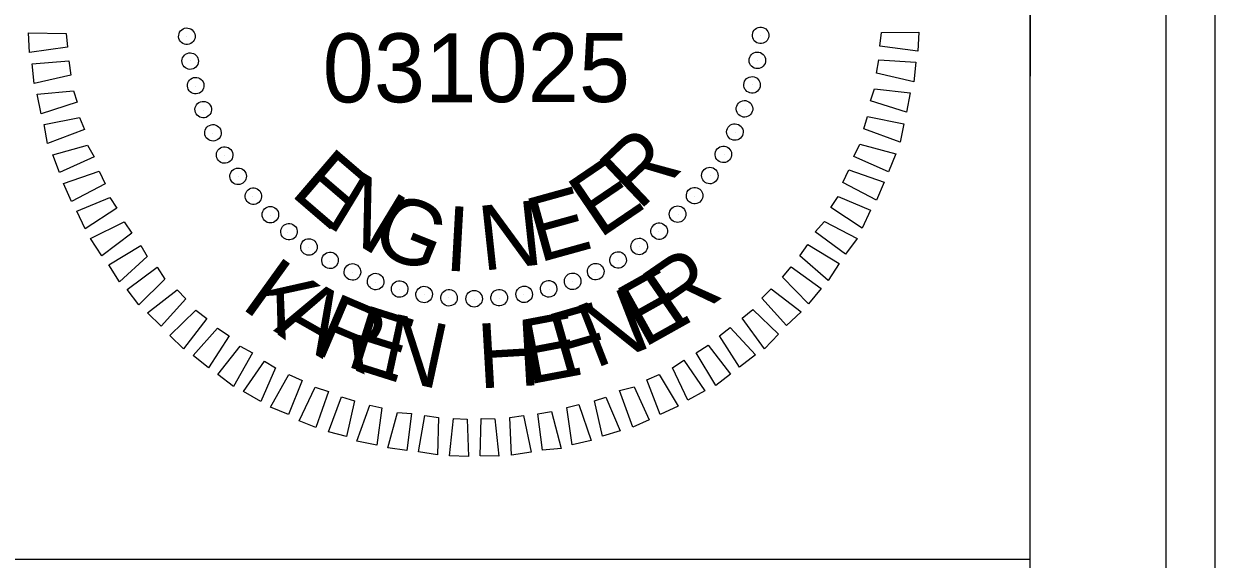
# Model space of a CAD drawing. Extents: x 2568837 to 2570520, y 536545 to 537640.
# Drawn here: x 2570410.9 to 2570520.2, y 537467.1 to 537516.2 of the extents above; entities that cross this region are included whole.
import ezdxf

# ---------------------------------------------------------------- set-up
doc = ezdxf.new("R2010")
doc.units = 0
for name, color, linetype in [('Default', 7, 'Continuous'), ('Sheet Plan CELL', 7, 'Continuous'), ('Sheet Plan Layout CELL', 7, 'Continuous'), ('Sheet Plot Border Inside CELL', 7, 'Continuous'), ('Sheet Plot Border Outside CELL', 7, 'Continuous')]:
    doc.layers.add(name, color=color, linetype=linetype)

msp = doc.modelspace()

# ---------------------------------------------------------------- linework, layer by layer
at = {"layer": 'Default'}
for p, q in [((2570425.81, 537515.02), (2570425.81, 537515.02)), ((2570425.81, 537515.02), (2570425.81, 537515.02)), ((2570478.5, 537515.12), (2570478.5, 537515.12)), ((2570478.5, 537515.12), (2570478.5, 537515.12)), ((2570426.17, 537512.81), (2570426.17, 537512.81)), ((2570426.17, 537512.81), (2570426.17, 537512.81)), ((2570478.17, 537512.85), (2570478.17, 537512.85)), ((2570478.17, 537512.85), (2570478.17, 537512.85)), ((2570426.63, 537510.5), (2570426.63, 537510.5)), ((2570426.63, 537510.5), (2570426.63, 537510.5)), ((2570477.74, 537510.63), (2570477.74, 537510.63)), ((2570477.74, 537510.63), (2570477.74, 537510.63)), ((2570427.31, 537508.3), (2570427.31, 537508.3)), ((2570427.31, 537508.3), (2570427.31, 537508.3)), ((2570477.05, 537508.4), (2570477.05, 537508.4)), ((2570477.05, 537508.4), (2570477.05, 537508.4)), ((2570428.19, 537506.16), (2570428.19, 537506.16)), ((2570428.19, 537506.16), (2570428.19, 537506.16)), ((2570476.14, 537506.27), (2570476.14, 537506.27)), ((2570476.14, 537506.27), (2570476.14, 537506.27)), ((2570429.28, 537504.18), (2570429.28, 537504.18)), ((2570429.28, 537504.18), (2570429.28, 537504.18)), ((2570475.12, 537504.2), (2570475.12, 537504.2)), ((2570475.12, 537504.2), (2570475.12, 537504.2)), ((2570430.53, 537502.2), (2570430.53, 537502.2)), ((2570430.53, 537502.2), (2570430.53, 537502.2)), ((2570473.84, 537502.28), (2570473.84, 537502.28)), ((2570473.84, 537502.28), (2570473.84, 537502.28)), ((2570431.88, 537500.38), (2570431.88, 537500.38)), ((2570431.88, 537500.38), (2570431.88, 537500.38)), ((2570472.45, 537500.35), (2570472.45, 537500.35)), ((2570472.45, 537500.35), (2570472.45, 537500.35)), ((2570433.5, 537498.67), (2570433.5, 537498.67)), ((2570433.5, 537498.67), (2570433.5, 537498.67)), ((2570470.91, 537498.74), (2570470.91, 537498.74)), ((2570470.91, 537498.74), (2570470.91, 537498.74)), ((2570435.1, 537497.12), (2570435.1, 537497.12)), ((2570435.1, 537497.12), (2570435.1, 537497.12)), ((2570469.14, 537497.13), (2570469.14, 537497.13)), ((2570469.14, 537497.13), (2570469.14, 537497.13)), ((2570437.03, 537495.74), (2570437.03, 537495.74)), ((2570437.03, 537495.74), (2570437.03, 537495.74)), ((2570467.38, 537495.78), (2570467.38, 537495.78)), ((2570467.38, 537495.78), (2570467.38, 537495.78)), ((2570438.95, 537494.45), (2570438.95, 537494.45)), ((2570438.95, 537494.45), (2570438.95, 537494.45)), ((2570465.4, 537494.53), (2570465.4, 537494.53)), ((2570465.4, 537494.53), (2570465.4, 537494.53)), ((2570441.02, 537493.39), (2570441.02, 537493.39)), ((2570441.02, 537493.39), (2570441.02, 537493.39)), ((2570463.36, 537493.44), (2570463.36, 537493.44)), ((2570463.36, 537493.44), (2570463.36, 537493.44)), ((2570443.1, 537492.48), (2570443.1, 537492.48)), ((2570443.1, 537492.48), (2570443.1, 537492.48)), ((2570445.38, 537491.84), (2570445.38, 537491.84)), ((2570445.38, 537491.84), (2570445.38, 537491.84)), ((2570459.07, 537491.88), (2570459.07, 537491.88)), ((2570459.07, 537491.88), (2570459.07, 537491.88)), ((2570461.22, 537492.56), (2570461.22, 537492.56)), ((2570461.22, 537492.56), (2570461.22, 537492.56)), ((2570447.6, 537491.4), (2570447.6, 537491.4)), ((2570447.6, 537491.4), (2570447.6, 537491.4)), ((2570449.87, 537491.08), (2570449.87, 537491.08)), ((2570449.87, 537491.08), (2570449.87, 537491.08)), ((2570452.19, 537490.96), (2570452.19, 537490.96)), ((2570452.19, 537490.96), (2570452.19, 537490.96)), ((2570454.51, 537491.06), (2570454.51, 537491.06)), ((2570454.51, 537491.06), (2570454.51, 537491.06)), ((2570456.76, 537491.42), (2570456.76, 537491.42)), ((2570456.76, 537491.42), (2570456.76, 537491.42))]:
    msp.add_line(p, q, dxfattribs=at)
for points in [[(2570414.87, 537514.08), (2570411.4, 537513.59), (2570411.31, 537515.38), (2570414.74, 537515.34)], [(2570489.56, 537515.43), (2570492.99, 537515.44), (2570492.91, 537513.7), (2570489.42, 537514.17)], [(2570415.18, 537511.5), (2570411.82, 537510.75), (2570411.63, 537512.54), (2570415, 537512.81)], [(2570489.34, 537512.9), (2570492.72, 537512.7), (2570492.54, 537510.91), (2570489.1, 537511.68)], [(2570488.92, 537510.26), (2570492.2, 537509.9), (2570491.86, 537508.1), (2570488.57, 537509.14)], [(2570415.75, 537509.04), (2570412.45, 537507.97), (2570412.1, 537509.76), (2570415.42, 537510.08)], [(2570416.43, 537506.52), (2570413.03, 537505.24), (2570412.73, 537506.97), (2570415.99, 537507.62)], [(2570488.28, 537507.71), (2570491.62, 537507.04), (2570491.28, 537505.35), (2570487.94, 537506.6)], [(2570417.32, 537504.01), (2570414.14, 537502.57), (2570413.53, 537504.2), (2570416.72, 537505.1)], [(2570487.59, 537505.17), (2570490.88, 537504.29), (2570490.22, 537502.64), (2570487.04, 537504.06)], [(2570418.32, 537501.55), (2570415.24, 537499.91), (2570414.52, 537501.58), (2570417.77, 537502.7)], [(2570486.58, 537502.83), (2570489.82, 537501.69), (2570489.11, 537500.04), (2570486.03, 537501.66)], [(2570419.41, 537499.3), (2570416.5, 537497.4), (2570415.73, 537499.02), (2570418.76, 537500.29)], [(2570485.58, 537500.39), (2570488.55, 537499.13), (2570487.79, 537497.48), (2570484.91, 537499.38)], [(2570484.35, 537498.1), (2570487.34, 537496.53), (2570486.26, 537495.08), (2570483.48, 537497.14)], [(2570420.78, 537497.01), (2570418.02, 537494.95), (2570416.99, 537496.52), (2570420.07, 537498.05)], [(2570482.81, 537495.97), (2570485.69, 537494.23), (2570484.67, 537492.68), (2570482.09, 537494.95)], [(2570422.19, 537494.87), (2570419.65, 537492.56), (2570418.67, 537494.12), (2570421.59, 537495.87)], [(2570423.81, 537492.8), (2570421.43, 537490.43), (2570420.35, 537491.84), (2570423.1, 537493.89)], [(2570481.27, 537493.94), (2570484.05, 537491.93), (2570482.86, 537490.54), (2570480.5, 537492.97)], [(2570425.74, 537490.99), (2570423.47, 537488.47), (2570422.23, 537489.71), (2570424.93, 537491.82)], [(2570479.46, 537491.9), (2570482.19, 537489.79), (2570480.85, 537488.55), (2570478.59, 537491.04)], [(2570427.67, 537489.18), (2570425.51, 537486.4), (2570424.27, 537487.64), (2570426.65, 537489.95)], [(2570477.76, 537490.02), (2570480.12, 537487.75), (2570478.83, 537486.41), (2570476.78, 537489.21)], [(2570429.7, 537487.59), (2570427.81, 537484.66), (2570426.41, 537485.79), (2570428.63, 537488.31)], [(2570475.68, 537488.35), (2570478, 537485.87), (2570476.54, 537484.73), (2570474.7, 537487.59)], [(2570431.84, 537486.05), (2570430.1, 537482.96), (2570428.66, 537484.04), (2570430.72, 537486.66)], [(2570473.66, 537486.73), (2570475.72, 537484.08), (2570474.36, 537483.05), (2570472.57, 537486.03)], [(2570433.97, 537484.66), (2570432.61, 537481.58), (2570431.01, 537482.5), (2570432.96, 537485.28)], [(2570471.42, 537485.37), (2570473.37, 537482.56), (2570471.81, 537481.69), (2570470.38, 537484.67)], [(2570436.42, 537483.5), (2570435.16, 537480.37), (2570433.51, 537481.07), (2570435.19, 537484.06)], [(2570469.18, 537484.06), (2570470.92, 537481.15), (2570469.25, 537480.38), (2570468.03, 537483.57)], [(2570438.81, 537482.49), (2570437.66, 537479.2), (2570436.12, 537479.8), (2570437.59, 537482.89)], [(2570466.88, 537482.91), (2570468.26, 537479.89), (2570466.74, 537479.22), (2570465.52, 537482.57)], [(2570441.2, 537481.64), (2570440.47, 537478.36), (2570438.82, 537478.8), (2570440.03, 537481.99)], [(2570464.27, 537481.97), (2570465.59, 537478.89), (2570463.97, 537478.38), (2570463.22, 537481.63)], [(2570443.73, 537481), (2570443.27, 537477.57), (2570441.42, 537477.95), (2570442.62, 537481.24)], [(2570459.28, 537480.66), (2570460.19, 537477.26), (2570458.46, 537477.12), (2570458.02, 537480.43)], [(2570461.8, 537481.29), (2570462.92, 537477.99), (2570461.19, 537477.59), (2570460.7, 537481.01)], [(2570446.43, 537480.47), (2570446.02, 537477.09), (2570444.28, 537477.33), (2570445.17, 537480.56)], [(2570448.92, 537480.1), (2570448.82, 537476.67), (2570447.08, 537476.96), (2570447.65, 537480.29)], [(2570451.55, 537479.94), (2570451.67, 537476.52), (2570449.93, 537476.59), (2570450.29, 537480.02)], [(2570454.08, 537479.99), (2570454.46, 537476.57), (2570452.73, 537476.59), (2570452.82, 537480.02)], [(2570456.71, 537480.3), (2570457.41, 537476.94), (2570455.62, 537476.64), (2570455.45, 537480.12)]]:
    msp.add_lwpolyline(points, close=True, dxfattribs=at)
for centre, major_axis in [((2570425.83, 537515.08), (-0.756, -0.067)), ((2570478.48, 537515.16), (0.756, -0.065)), ((2570426.13, 537512.8), (-0.747, -0.133)), ((2570478.18, 537512.87), (0.747, -0.131)), ((2570426.64, 537510.55), (-0.733, -0.197)), ((2570477.69, 537510.62), (0.733, -0.195)), ((2570427.33, 537508.35), (-0.713, -0.26)), ((2570477, 537508.42), (0.713, -0.258)), ((2570428.22, 537506.22), (-0.687, -0.322)), ((2570476.12, 537506.29), (0.688, -0.32)), ((2570429.29, 537504.18), (-0.656, -0.38)), ((2570475.06, 537504.24), (0.658, -0.378)), ((2570430.53, 537502.23), (-0.621, -0.436)), ((2570473.82, 537502.3), (0.622, -0.434)), ((2570431.93, 537500.41), (-0.58, -0.488)), ((2570472.42, 537500.46), (0.582, -0.487)), ((2570433.49, 537498.71), (-0.536, -0.537)), ((2570470.86, 537498.76), (0.537, -0.536)), ((2570435.2, 537497.15), (-0.487, -0.582)), ((2570469.17, 537497.2), (0.488, -0.58)), ((2570437.03, 537495.75), (-0.434, -0.622)), ((2570467.34, 537495.8), (0.436, -0.621)), ((2570438.97, 537494.52), (-0.378, -0.658)), ((2570465.4, 537494.56), (0.38, -0.656)), ((2570441.02, 537493.46), (-0.32, -0.688)), ((2570463.35, 537493.49), (0.322, -0.687)), ((2570443.15, 537492.58), (-0.258, -0.713)), ((2570445.35, 537491.89), (-0.195, -0.733)), ((2570459.03, 537491.91), (0.197, -0.733)), ((2570461.23, 537492.6), (0.26, -0.713)), ((2570447.6, 537491.39), (-0.131, -0.747)), ((2570449.89, 537491.09), (-0.065, -0.756)), ((2570452.19, 537491), (0.001, -0.759)), ((2570454.49, 537491.1), (0.067, -0.756)), ((2570456.78, 537491.4), (0.133, -0.747))]:
    msp.add_ellipse(centre, major_axis=major_axis, ratio=0.999708, dxfattribs=at)
at = {"layer": 'Sheet Plan CELL'}
for points in [[(2570503.22, 537617.15), (2569003.18, 537617.15), (2569003.18, 536567.15), (2570503.19, 536567.15)], [(2570403.19, 537579.59), (2570503.18, 537579.6), (2570503.19, 537467.09), (2570403.19, 537467.08)]]:
    msp.add_lwpolyline(points, close=True, dxfattribs=at)
at = {"layer": 'Sheet Plan Layout CELL'}
msp.add_lwpolyline([(2570263.93, 537405.66), (2570503.2, 537405.66), (2570503.23, 537617.15), (2570263.93, 537617.15)], close=True, dxfattribs=at)
at = {"layer": 'Sheet Plot Border Inside CELL'}
msp.add_lwpolyline([(2568849.69, 536564.64), (2570515.68, 536564.65), (2570515.69, 537619.64), (2568849.69, 537619.64)], close=True, dxfattribs=at)
at = {"layer": 'Sheet Plot Border Outside CELL'}
msp.add_lwpolyline([(2568836.69, 536544.64), (2570520.19, 536544.64), (2570520.19, 537639.64), (2568836.69, 537639.64)], close=True, dxfattribs=at)

# ---------------------------------------------------------------- texts
at = {"layer": 'Default'}
for s, height, rotation, p in [('031025', 6.322, 0.081, (2570438.29, 537509.01)), ('R', 5.94, 43.5624, (2570467.32, 537498.99)), ('E', 5.94, 319.3578, (2570435.2, 537500.6)), ('E', 5.94, 34.205, (2570463.67, 537496.45)), ('N', 5.94, 328.7149, (2570438.41, 537497.82)), ('G', 5.94, 338.0712, (2570442.46, 537495.52)), ('E', 5.94, 15.4927, (2570458.13, 537494.29)), ('I', 5.94, 356.7822, (2570449.4, 537493.6)), ('N', 5.94, 6.1373, (2570452.93, 537493.56)), ('R', 5.94, 34.4906, (2570470.5, 537488)), ('K', 5.94, 324.2363, (2570430.68, 537490.22)), ('E', 5.94, 29.2101, (2570467.72, 537486.44)), ('A', 5.94, 330.3893, (2570433.72, 537488.07)), ('N', 5.94, 21.2433, (2570463.28, 537484.58)), ('R', 5.94, 336.9555, (2570437.2, 537486.16)), ('F', 5.94, 16.0317, (2570460.25, 537483.71)), ('E', 5.94, 342.5116, (2570440.29, 537484.85)), ('N', 5.94, 347.7922, (2570443.34, 537483.9)), ('E', 5.94, 10.7511, (2570457.11, 537483.11)), ('H', 5.94, 3.3354, (2570452.64, 537482.76))]:
    msp.add_text(s, height=height, rotation=rotation, dxfattribs=at).set_placement(p)

doc.saveas('drawing.dxf')
